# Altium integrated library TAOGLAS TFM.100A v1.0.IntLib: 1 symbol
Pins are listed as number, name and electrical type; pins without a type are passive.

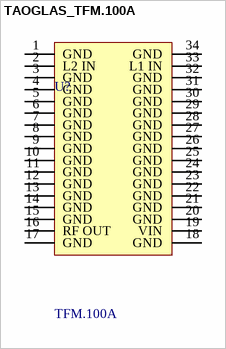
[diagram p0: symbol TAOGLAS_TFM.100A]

## TAOGLAS_TFM.100A
designator U?, comment TFM.100A
Surface mount GNSS front-end module covering L1/L2; MFG: Taoglas; Temp_High: +85C; Temp_Low: -40C; ComponentLibStatus: Created
footprint TAOGLAS_TFM.100A (Surface mount GNSS front-end module covering L1/L2)
pins: 1 GND, 2 L2 IN, 3 GND, 4 GND, 5 GND, 6 GND, 7 GND, 8 GND, 9 GND, 10 GND, 11 GND, 12 GND, 13 GND, 14 GND, 15 GND, 16 RF OUT, 17 GND, 18 GND, 19 VIN, 20 GND, 21 GND, 22 GND, 23 GND, 24 GND, 25 GND, 26 GND, 27 GND, 28 GND, 29 GND, 30 GND, 31 GND, 32 GND, 33 L1 IN, 34 GND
